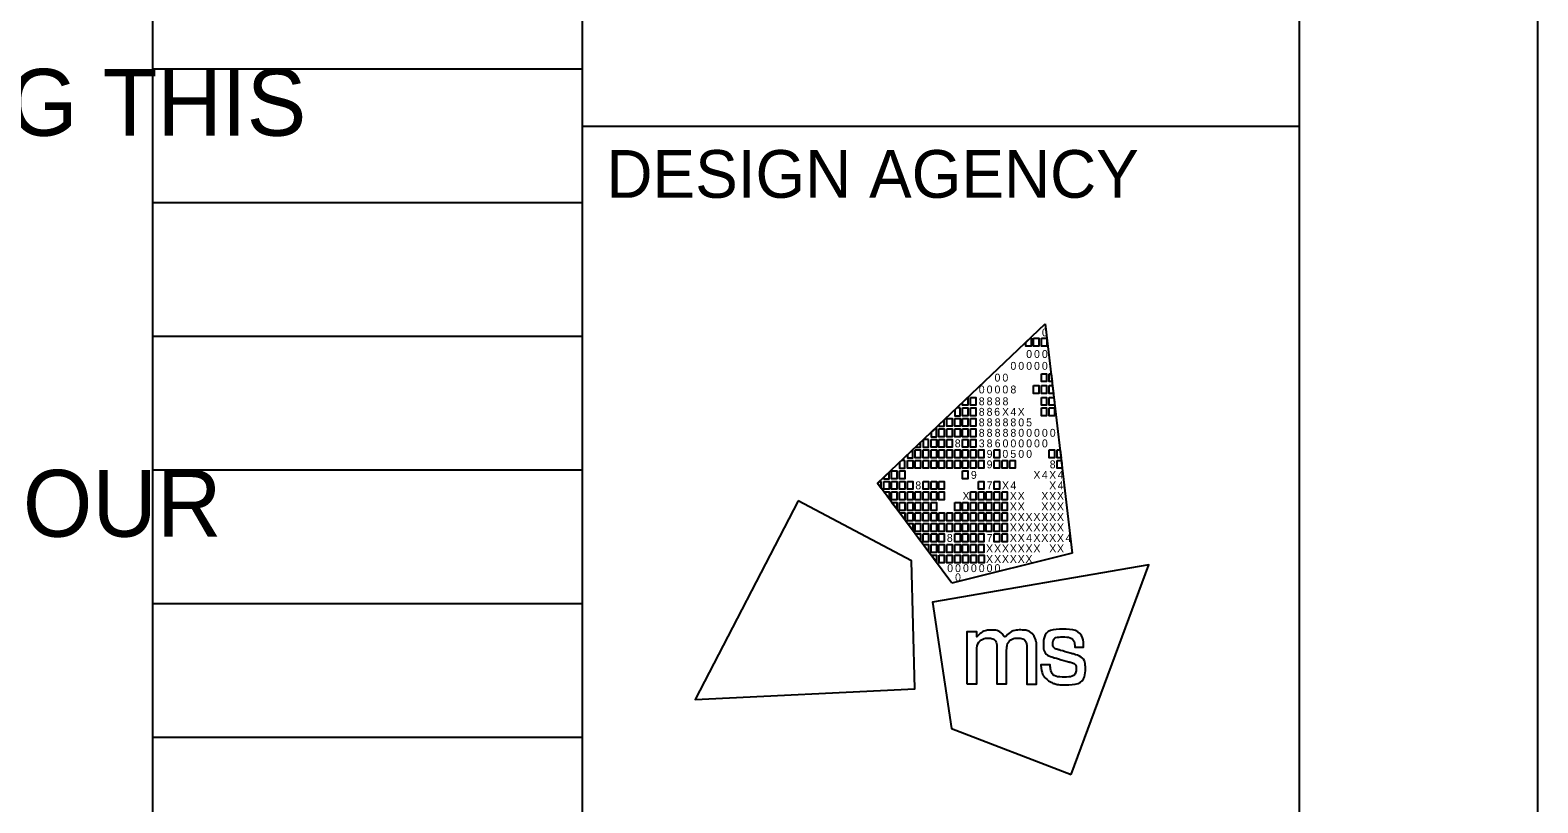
# Model space of a CAD drawing. Extents: x 0 to 34, y -9.1 to 22.
# Drawn here: x 30.843 to 34, y 3.082 to 4.701 of the extents above; entities that cross this region are included whole.
import ezdxf

# ---------------------------------------------------------------- set-up
doc = ezdxf.new("R2010")
doc.units = 0
for name, color, linetype in [('SH_Border', 7, 'Continuous'), ('SH_Cut_Line', 7, 'Continuous'), ('SH_Data', 7, 'Continuous'), ('SH_Text', 7, 'Continuous')]:
    doc.layers.add(name, color=color, linetype=linetype)

msp = doc.modelspace()

# ---------------------------------------------------------------- linework, layer by layer
at = {"layer": 'SH_Border'}
for p, q in [((32, 0.5), (32, 21.5)), ((32, 4.5), (33.5, 4.5)), ((32.6175, 3.7519), (32.9688, 4.0861)), ((32.9688, 4.0861), (32.9688, 4.0861)), ((32.9688, 4.0861), (33.0253, 3.6052)), ((32.773, 3.543), (32.6175, 3.7519)), ((33.0253, 3.6052), (32.773, 3.543))]:
    msp.add_line(p, q, dxfattribs=at)
for points in [[(1.5, 21.5), (33.5, 21.5), (33.5, 0.5), (1.5, 0.5)], [(32.9279, 4.0472), (32.9369, 4.0558), (32.9389, 4.0558), (32.9389, 4.0393), (32.9279, 4.0393)], [(32.9444, 4.0558), (32.9554, 4.0558), (32.9554, 4.0393), (32.9444, 4.0393)], [(32.9609, 4.0558), (32.9719, 4.0558), (32.9719, 4.0393), (32.9609, 4.0393)], [(32.9606, 3.9815), (32.9716, 3.9815), (32.9716, 3.965), (32.9606, 3.965)], [(32.9771, 3.9815), (32.9811, 3.9815), (32.983, 3.965), (32.9771, 3.965)], [(32.9441, 3.9567), (32.9551, 3.9567), (32.9551, 3.9402), (32.9441, 3.9402)], [(32.9606, 3.9567), (32.9716, 3.9567), (32.9716, 3.9402), (32.9606, 3.9402)], [(32.9771, 3.9567), (32.984, 3.9567), (32.9859, 3.9402), (32.9771, 3.9402)], [(32.7953, 3.9211), (32.8064, 3.9316), (32.8064, 3.9154), (32.7953, 3.9154)], [(32.8123, 3.9319), (32.8233, 3.9319), (32.8233, 3.9154), (32.8123, 3.9154)], [(32.9606, 3.9319), (32.9716, 3.9319), (32.9716, 3.9154), (32.9606, 3.9154)], [(32.9771, 3.9319), (32.9869, 3.9319), (32.9881, 3.9218), (32.9881, 3.9154), (32.9771, 3.9154)], [(32.7627, 3.8879), (32.7737, 3.8879), (32.7737, 3.8714), (32.7627, 3.8714)], [(32.7793, 3.8879), (32.7903, 3.8879), (32.7903, 3.8714), (32.7793, 3.8714)], [(32.7958, 3.9099), (32.8068, 3.9099), (32.8068, 3.8934), (32.7958, 3.8934)], [(32.7958, 3.8879), (32.8068, 3.8879), (32.8068, 3.8714), (32.7958, 3.8714)], [(32.8123, 3.9099), (32.8233, 3.9099), (32.8233, 3.8934), (32.8123, 3.8934)], [(32.8123, 3.8879), (32.8233, 3.8879), (32.8233, 3.8714), (32.8123, 3.8714)], [(32.9606, 3.9099), (32.9716, 3.9099), (32.9716, 3.8934), (32.9606, 3.8934)], [(32.9771, 3.9099), (32.9881, 3.9099), (32.9881, 3.8934), (32.9771, 3.8934)], [(32.7462, 3.8659), (32.7572, 3.8659), (32.7572, 3.8494), (32.7462, 3.8494)], [(32.7627, 3.8659), (32.7737, 3.8659), (32.7737, 3.8494), (32.7627, 3.8494)], [(32.7793, 3.8659), (32.7903, 3.8659), (32.7903, 3.8494), (32.7793, 3.8494)], [(32.7958, 3.8659), (32.8068, 3.8659), (32.8068, 3.8494), (32.7958, 3.8494)], [(32.8123, 3.8659), (32.8233, 3.8659), (32.8233, 3.8494), (32.8123, 3.8494)], [(32.6967, 3.8218), (32.7077, 3.8218), (32.7077, 3.8053), (32.6967, 3.8053)], [(32.7132, 3.8218), (32.7242, 3.8218), (32.7242, 3.8053), (32.7132, 3.8053)], [(32.7297, 3.8439), (32.7407, 3.8439), (32.7407, 3.8273), (32.7297, 3.8273)], [(32.7297, 3.8218), (32.7407, 3.8218), (32.7407, 3.8053), (32.7297, 3.8053)], [(32.7462, 3.8439), (32.7572, 3.8439), (32.7572, 3.8273), (32.7462, 3.8273)], [(32.7462, 3.8218), (32.7572, 3.8218), (32.7572, 3.8053), (32.7462, 3.8053)], [(32.7627, 3.8439), (32.7737, 3.8439), (32.7737, 3.8273), (32.7627, 3.8273)], [(32.7627, 3.8218), (32.7737, 3.8218), (32.7737, 3.8053), (32.7627, 3.8053)], [(32.7793, 3.8218), (32.7903, 3.8218), (32.7903, 3.8053), (32.7793, 3.8053)], [(32.7958, 3.8439), (32.8068, 3.8439), (32.8068, 3.8273), (32.7958, 3.8273)], [(32.7958, 3.8218), (32.8068, 3.8218), (32.8068, 3.8053), (32.7958, 3.8053)], [(32.8123, 3.8439), (32.8233, 3.8439), (32.8233, 3.8273), (32.8123, 3.8273)], [(32.8123, 3.8218), (32.8233, 3.8218), (32.8233, 3.8053), (32.8123, 3.8053)], [(32.8288, 3.8218), (32.8398, 3.8218), (32.8398, 3.8053), (32.8288, 3.8053)], [(32.8618, 3.8218), (32.8728, 3.8218), (32.8728, 3.8053), (32.8618, 3.8053)], [(32.9771, 3.8218), (32.9881, 3.8218), (32.9881, 3.8053), (32.9771, 3.8053)], [(32.9935, 3.8218), (32.9998, 3.8218), (33.0018, 3.8053), (32.9935, 3.8053)], [(32.6802, 3.7998), (32.6912, 3.7998), (32.6912, 3.7833), (32.6802, 3.7833)], [(32.6967, 3.7998), (32.7077, 3.7998), (32.7077, 3.7833), (32.6967, 3.7833)], [(32.7132, 3.7998), (32.7242, 3.7998), (32.7242, 3.7833), (32.7132, 3.7833)], [(32.7297, 3.7998), (32.7407, 3.7998), (32.7407, 3.7833), (32.7297, 3.7833)], [(32.7462, 3.7998), (32.7572, 3.7998), (32.7572, 3.7833), (32.7462, 3.7833)], [(32.7627, 3.7998), (32.7737, 3.7998), (32.7737, 3.7833), (32.7627, 3.7833)], [(32.7793, 3.7998), (32.7903, 3.7998), (32.7903, 3.7833), (32.7793, 3.7833)], [(32.7958, 3.7998), (32.8068, 3.7998), (32.8068, 3.7833), (32.7958, 3.7833)], [(32.8123, 3.7998), (32.8233, 3.7998), (32.8233, 3.7833), (32.8123, 3.7833)], [(32.8288, 3.7998), (32.8398, 3.7998), (32.8398, 3.7833), (32.8288, 3.7833)], [(32.8618, 3.7998), (32.8728, 3.7998), (32.8728, 3.7833), (32.8618, 3.7833)], [(32.8783, 3.7998), (32.8893, 3.7998), (32.8893, 3.7833), (32.8783, 3.7833)], [(32.8947, 3.7998), (32.9057, 3.7998), (32.9057, 3.7833), (32.8947, 3.7833)], [(32.9935, 3.7998), (33.0024, 3.7998), (33.0044, 3.7833), (32.9935, 3.7833)], [(32.6471, 3.7778), (32.6581, 3.7778), (32.6581, 3.7613), (32.6471, 3.7613)], [(32.6637, 3.7778), (32.6747, 3.7778), (32.6747, 3.7613), (32.6637, 3.7613)], [(32.7958, 3.7778), (32.8068, 3.7778), (32.8068, 3.7613), (32.7958, 3.7613)], [(32.6306, 3.7558), (32.6416, 3.7558), (32.6416, 3.7393), (32.6306, 3.7393)], [(32.6306, 3.7338), (32.6416, 3.7338), (32.6416, 3.72)], [(32.6471, 3.7558), (32.6581, 3.7558), (32.6581, 3.7393), (32.6471, 3.7393)], [(32.6471, 3.7338), (32.6581, 3.7338), (32.6581, 3.7173), (32.6471, 3.7173)], [(32.6637, 3.7558), (32.6747, 3.7558), (32.6747, 3.7393), (32.6637, 3.7393)], [(32.6637, 3.7338), (32.6747, 3.7338), (32.6747, 3.7173), (32.6637, 3.7173)], [(32.6802, 3.7558), (32.6912, 3.7558), (32.6912, 3.7393), (32.6802, 3.7393)], [(32.6802, 3.7338), (32.6912, 3.7338), (32.6912, 3.7173), (32.6802, 3.7173)], [(32.6967, 3.7338), (32.7077, 3.7338), (32.7077, 3.7173), (32.6967, 3.7173)], [(32.7132, 3.7558), (32.7242, 3.7558), (32.7242, 3.7393), (32.7132, 3.7393)], [(32.7132, 3.7338), (32.7242, 3.7338), (32.7242, 3.7173), (32.7132, 3.7173)], [(32.7297, 3.7558), (32.7407, 3.7558), (32.7407, 3.7393), (32.7297, 3.7393)], [(32.7297, 3.7338), (32.7407, 3.7338), (32.7407, 3.7173), (32.7297, 3.7173)], [(32.7462, 3.7558), (32.7572, 3.7558), (32.7572, 3.7393), (32.7462, 3.7393)], [(32.7462, 3.7338), (32.7572, 3.7338), (32.7572, 3.7173), (32.7462, 3.7173)], [(32.8123, 3.7338), (32.8233, 3.7338), (32.8233, 3.7173), (32.8123, 3.7173)], [(32.8288, 3.7558), (32.8398, 3.7558), (32.8398, 3.7393), (32.8288, 3.7393)], [(32.8288, 3.7338), (32.8398, 3.7338), (32.8398, 3.7173), (32.8288, 3.7173)], [(32.8453, 3.7338), (32.8563, 3.7338), (32.8563, 3.7173), (32.8453, 3.7173)], [(32.8618, 3.7558), (32.8728, 3.7558), (32.8728, 3.7393), (32.8618, 3.7393)], [(32.8618, 3.7338), (32.8728, 3.7338), (32.8728, 3.7173), (32.8618, 3.7173)], [(32.8783, 3.7338), (32.8893, 3.7338), (32.8893, 3.7173), (32.8783, 3.7173)], [(32.6471, 3.7117), (32.6581, 3.7117), (32.6581, 3.698)], [(32.6637, 3.7117), (32.6747, 3.7117), (32.6747, 3.6952), (32.6637, 3.6952)], [(32.6802, 3.7117), (32.6912, 3.7117), (32.6912, 3.6952), (32.6802, 3.6952)], [(32.6967, 3.7117), (32.7077, 3.7117), (32.7077, 3.6952), (32.6967, 3.6952)], [(32.7132, 3.7117), (32.7242, 3.7117), (32.7242, 3.6952), (32.7132, 3.6952)], [(32.7297, 3.7117), (32.7407, 3.7117), (32.7407, 3.6952), (32.7297, 3.6952)], [(32.7793, 3.7117), (32.7903, 3.7117), (32.7903, 3.6952), (32.7793, 3.6952)], [(32.7958, 3.7117), (32.8068, 3.7117), (32.8068, 3.6952), (32.7958, 3.6952)], [(32.8123, 3.7117), (32.8233, 3.7117), (32.8233, 3.6952), (32.8123, 3.6952)], [(32.8288, 3.7117), (32.8398, 3.7117), (32.8398, 3.6952), (32.8288, 3.6952)], [(32.8453, 3.7117), (32.8563, 3.7117), (32.8563, 3.6952), (32.8453, 3.6952)], [(32.8618, 3.7117), (32.8728, 3.7117), (32.8728, 3.6952), (32.8618, 3.6952)], [(32.8783, 3.7117), (32.8893, 3.7117), (32.8893, 3.6952), (32.8783, 3.6952)], [(32.6637, 3.6897), (32.6747, 3.6897), (32.6747, 3.676)], [(32.6747, 3.6897), (32.6747, 3.6897), (32.6747, 3.6897)], [(32.6802, 3.6897), (32.6912, 3.6897), (32.6912, 3.6732), (32.6802, 3.6732)], [(32.6802, 3.6677), (32.6912, 3.6677), (32.6912, 3.654)], [(32.6967, 3.6897), (32.7077, 3.6897), (32.7077, 3.6732), (32.6967, 3.6732)], [(32.6967, 3.6677), (32.7077, 3.6677), (32.7077, 3.6512), (32.6967, 3.6512)], [(32.7132, 3.6897), (32.7242, 3.6897), (32.7242, 3.6732), (32.7132, 3.6732)], [(32.7132, 3.6677), (32.7242, 3.6677), (32.7242, 3.6512), (32.7132, 3.6512)], [(32.7297, 3.6897), (32.7407, 3.6897), (32.7407, 3.6732), (32.7297, 3.6732)], [(32.7297, 3.6677), (32.7407, 3.6677), (32.7407, 3.6512), (32.7297, 3.6512)], [(32.7462, 3.6897), (32.7572, 3.6897), (32.7572, 3.6732), (32.7462, 3.6732)], [(32.7462, 3.6677), (32.7572, 3.6677), (32.7572, 3.6512), (32.7462, 3.6512)], [(32.7627, 3.6897), (32.7737, 3.6897), (32.7737, 3.6732), (32.7627, 3.6732)], [(32.7627, 3.6677), (32.7737, 3.6677), (32.7737, 3.6512), (32.7627, 3.6512)], [(32.7793, 3.6897), (32.7903, 3.6897), (32.7903, 3.6732), (32.7793, 3.6732)], [(32.7793, 3.6677), (32.7903, 3.6677), (32.7903, 3.6512), (32.7793, 3.6512)], [(32.7958, 3.6897), (32.8068, 3.6897), (32.8068, 3.6732), (32.7958, 3.6732)], [(32.7958, 3.6677), (32.8068, 3.6677), (32.8068, 3.6512), (32.7958, 3.6512)], [(32.8123, 3.6897), (32.8233, 3.6897), (32.8233, 3.6732), (32.8123, 3.6732)], [(32.8123, 3.6677), (32.8233, 3.6677), (32.8233, 3.6512), (32.8123, 3.6512)], [(32.8288, 3.6897), (32.8398, 3.6897), (32.8398, 3.6732), (32.8288, 3.6732)], [(32.8288, 3.6677), (32.8398, 3.6677), (32.8398, 3.6512), (32.8288, 3.6512)], [(32.8453, 3.6897), (32.8563, 3.6897), (32.8563, 3.6732), (32.8453, 3.6732)], [(32.8453, 3.6677), (32.8563, 3.6677), (32.8563, 3.6512), (32.8453, 3.6512)], [(32.8618, 3.6897), (32.8728, 3.6897), (32.8728, 3.6732), (32.8618, 3.6732)], [(32.8618, 3.6677), (32.8728, 3.6677), (32.8728, 3.6512), (32.8618, 3.6512)], [(32.8783, 3.6897), (32.8893, 3.6897), (32.8893, 3.6732), (32.8783, 3.6732)], [(32.8783, 3.6677), (32.8893, 3.6677), (32.8893, 3.6512), (32.8783, 3.6512)], [(32.7077, 3.6305), (32.6965, 3.6457), (32.7077, 3.6457)], [(32.7132, 3.6457), (32.7242, 3.6457), (32.7242, 3.6292), (32.7132, 3.6292)], [(32.7297, 3.6457), (32.7407, 3.6457), (32.7407, 3.6292), (32.7297, 3.6292)], [(32.7462, 3.6457), (32.7572, 3.6457), (32.7572, 3.6292), (32.7462, 3.6292)], [(32.7793, 3.6457), (32.7903, 3.6457), (32.7903, 3.6292), (32.7793, 3.6292)], [(32.7958, 3.6457), (32.8068, 3.6457), (32.8068, 3.6292), (32.7958, 3.6292)], [(32.8123, 3.6457), (32.8233, 3.6457), (32.8233, 3.6292), (32.8123, 3.6292)], [(32.8288, 3.6457), (32.8398, 3.6457), (32.8398, 3.6292), (32.8288, 3.6292)], [(32.8618, 3.6457), (32.8728, 3.6457), (32.8728, 3.6292), (32.8618, 3.6292)], [(32.8783, 3.6457), (32.8893, 3.6457), (32.8893, 3.6292), (32.8783, 3.6292)], [(32.724, 3.6082), (32.7132, 3.6237), (32.7242, 3.6237)], [(32.7297, 3.6237), (32.7407, 3.6237), (32.7407, 3.6072), (32.7297, 3.6072)], [(32.7302, 3.6017), (32.7407, 3.6017), (32.7408, 3.5875)], [(32.7462, 3.6237), (32.7572, 3.6237), (32.7572, 3.6072), (32.7462, 3.6072)], [(32.7463, 3.6017), (32.7573, 3.6017), (32.7573, 3.5852), (32.7463, 3.5852)], [(32.7627, 3.6237), (32.7737, 3.6237), (32.7737, 3.6072), (32.7627, 3.6072)], [(32.763, 3.6017), (32.774, 3.6017), (32.774, 3.5852), (32.763, 3.5852)], [(32.7793, 3.6237), (32.7903, 3.6237), (32.7903, 3.6072), (32.7793, 3.6072)], [(32.7794, 3.6017), (32.7904, 3.6017), (32.7904, 3.5852), (32.7794, 3.5852)], [(32.7958, 3.6237), (32.8068, 3.6237), (32.8068, 3.6072), (32.7958, 3.6072)], [(32.796, 3.6017), (32.807, 3.6017), (32.807, 3.5852), (32.796, 3.5852)], [(32.8123, 3.6237), (32.8233, 3.6237), (32.8233, 3.6072), (32.8123, 3.6072)], [(32.8129, 3.6017), (32.8239, 3.6017), (32.8239, 3.5851), (32.8129, 3.5851)], [(32.8288, 3.6237), (32.8398, 3.6237), (32.8398, 3.6072), (32.8288, 3.6072)], [(32.8296, 3.6017), (32.8406, 3.6017), (32.8406, 3.5851), (32.8296, 3.5851)]]:
    msp.add_lwpolyline(points, close=True, dxfattribs=at)
for points in [[(32.7572, 3.8849), (32.7462, 3.8744), (32.7462, 3.8714), (32.7572, 3.8714), (32.7572, 3.8849)], [(32.7903, 3.9099), (32.7836, 3.9099), (32.7793, 3.9058), (32.7793, 3.8934), (32.7903, 3.8934), (32.7903, 3.9099)], [(32.7407, 3.8691), (32.7297, 3.8587), (32.7297, 3.8494), (32.7407, 3.8494), (32.7407, 3.8691)], [(32.6912, 3.822), (32.6802, 3.8115), (32.6802, 3.8053), (32.6912, 3.8053), (32.6912, 3.822)], [(32.7077, 3.8377), (32.6968, 3.8273), (32.7077, 3.8273), (32.7077, 3.8377)], [(32.7242, 3.8439), (32.7141, 3.8439), (32.7132, 3.843), (32.7132, 3.8273), (32.7242, 3.8273), (32.7242, 3.8439)], [(32.6747, 3.7998), (32.6679, 3.7998), (32.6637, 3.7958), (32.6637, 3.7833), (32.6747, 3.7833), (32.6747, 3.7998)], [(32.6416, 3.7749), (32.6306, 3.7644), (32.6306, 3.7613), (32.6416, 3.7613), (32.6416, 3.7749)], [(32.6251, 3.7558), (32.6216, 3.7558), (32.6175, 3.7519), (32.6251, 3.7417), (32.6251, 3.7558)], [(32.4512, 3.7149), (32.2359, 3.2988), (32.6956, 3.3215), (32.6884, 3.5892), (32.4512, 3.7149)], [(33.0229, 3.1422), (33.1859, 3.5814), (32.7324, 3.5029), (32.7722, 3.2381), (33.0229, 3.1422)]]:
    msp.add_lwpolyline(points, dxfattribs=at)
for points in [[(32.8048, 3.3315), (32.8048, 3.3315), (32.8048, 3.4409), (32.8048, 3.4409), (32.8048, 3.4409), (32.8255, 3.4409), (32.8255, 3.4409), (32.8255, 3.4409), (32.8255, 3.4297), (32.8255, 3.4297), (32.8346, 3.4399), (32.8457, 3.4445), (32.8555, 3.4445), (32.8688, 3.4445), (32.8791, 3.4372), (32.8837, 3.4266), (32.8915, 3.4381), (32.905, 3.4446), (32.9166, 3.4446), (32.9325, 3.4446), (32.9451, 3.435), (32.9494, 3.4213), (32.9494, 3.4212), (32.9494, 3.4212), (32.9494, 3.4212), (32.9501, 3.419), (32.9506, 3.4172), (32.9506, 3.4071), (32.9506, 3.4071), (32.9506, 3.3314), (32.9506, 3.3314), (32.9506, 3.3314), (32.9303, 3.3314), (32.9303, 3.3314), (32.9303, 3.3314), (32.9303, 3.4048), (32.9303, 3.4048), (32.9303, 3.4201), (32.9219, 3.4274), (32.911, 3.4274), (32.8995, 3.4274), (32.8879, 3.4171), (32.8879, 3.4001), (32.8879, 3.4001), (32.8879, 3.3315), (32.8879, 3.3315), (32.8879, 3.3315), (32.8674, 3.3315), (32.8674, 3.3315), (32.8674, 3.3315), (32.8674, 3.4059), (32.8674, 3.4059), (32.8674, 3.4203), (32.8588, 3.4274), (32.8496, 3.4274), (32.8384, 3.4274), (32.8254, 3.417), (32.8254, 3.3962), (32.8254, 3.3962), (32.8254, 3.3315), (32.8254, 3.3315), (32.8254, 3.3315), (32.8048, 3.3315), (32.8048, 3.3315)], [(32.9595, 3.3709), (32.9595, 3.3709), (32.9595, 3.3717), (32.9595, 3.3717), (32.9595, 3.3717), (32.9603, 3.3717), (32.9603, 3.3717), (32.9603, 3.3717), (32.9783, 3.3717), (32.9783, 3.3717), (32.9783, 3.3717), (32.9789, 3.3717), (32.9789, 3.3717), (32.9789, 3.3717), (32.979, 3.371), (32.979, 3.371), (32.9803, 3.3554), (32.9887, 3.346), (33.009, 3.346), (33.0273, 3.346), (33.0333, 3.3554), (33.0333, 3.3631), (33.0333, 3.3732), (33.0256, 3.3758), (33.0175, 3.378), (33.0175, 3.378), (32.987, 3.3867), (32.987, 3.3867), (32.972, 3.3909), (32.9648, 3.4019), (32.9648, 3.4142), (32.9648, 3.4303), (32.9768, 3.4462), (33.0052, 3.4462), (33.0348, 3.4462), (33.0489, 3.4285), (33.0489, 3.4095), (33.0489, 3.4095), (33.0489, 3.4087), (33.0489, 3.4087), (33.0489, 3.4087), (33.0482, 3.4087), (33.0482, 3.4087), (33.0482, 3.4087), (33.0312, 3.4087), (33.0312, 3.4087), (33.0312, 3.4087), (33.0305, 3.4087), (33.0305, 3.4087), (33.0305, 3.4087), (33.0305, 3.4094), (33.0305, 3.4094), (33.0301, 3.4208), (33.0226, 3.43), (33.0056, 3.43), (32.9891, 3.43), (32.9843, 3.4218), (32.9843, 3.4157), (32.9843, 3.4108), (32.9869, 3.4059), (32.9959, 3.4033), (32.9959, 3.4033), (33.0255, 3.3948), (33.0255, 3.3948), (33.0462, 3.3889), (33.0527, 3.3777), (33.0527, 3.3639), (33.0527, 3.3462), (33.041, 3.3298), (33.0087, 3.3298), (32.9952, 3.3298), (32.9877, 3.3321), (32.9823, 3.3348), (32.969, 3.3414), (32.9609, 3.3536), (32.9595, 3.3709)]]:
    msp.add_open_spline(points, degree=3, dxfattribs=at)
at = {"layer": 'SH_Cut_Line'}
msp.add_lwpolyline([(0, 0), (34, 0), (34, 22), (0, 22)], close=True, dxfattribs=at)
at = {"layer": 'SH_Data'}
for p, q in [((31.1, 0.98), (31.1, 21.14)), ((32, 0.98), (32, 21.14)), ((31.1, 4.62), (32, 4.62)), ((31.1, 4.34), (32, 4.34)), ((31.1, 4.06), (32, 4.06)), ((31.1, 3.78), (32, 3.78)), ((31.1, 3.5), (32, 3.5)), ((32.75, 3.5), (32.75, 3.5)), ((31.1, 3.22), (32, 3.22))]:
    msp.add_line(p, q, dxfattribs=at)

# ---------------------------------------------------------------- texts
at = {"layer": 'SH_Border'}
for s, p in [('0', (32.9617, 4.0597)), ('0', (32.9288, 4.0145)), ('0', (32.9452, 4.0145)), ('0', (32.9617, 4.0145)), ('0', (32.8625, 3.965)), ('0', (32.879, 3.965)), ('0', (32.8958, 3.9897)), ('0', (32.9123, 3.9897)), ('0', (32.9288, 3.9897)), ('0', (32.9452, 3.9897)), ('0', (32.9617, 3.9897)), ('0', (32.8295, 3.9402)), ('0', (32.846, 3.9402)), ('0', (32.8625, 3.9402)), ('0', (32.879, 3.9402)), ('8', (32.8958, 3.9402)), ('8', (32.8295, 3.9154)), ('8', (32.846, 3.9154)), ('8', (32.8628, 3.9154)), ('8', (32.8793, 3.9154)), ('8', (32.8295, 3.8934)), ('8', (32.8295, 3.8713)), ('8', (32.846, 3.8934)), ('8', (32.846, 3.8713)), ('6', (32.8618, 3.8934)), ('8', (32.8628, 3.8713)), ('X', (32.8781, 3.8934)), ('8', (32.8794, 3.8713)), ('4', (32.8958, 3.8934)), ('8', (32.8958, 3.8713)), ('X', (32.911, 3.8934)), ('0', (32.9123, 3.8713)), ('5', (32.9287, 3.8713)), ('8', (32.8295, 3.8494)), ('8', (32.846, 3.8494)), ('8', (32.8628, 3.8494)), ('8', (32.8794, 3.8494)), ('8', (32.8958, 3.8494)), ('0', (32.9123, 3.8494)), ('0', (32.9288, 3.8494)), ('0', (32.9452, 3.8494)), ('0', (32.9617, 3.8494)), ('0', (32.9782, 3.8494)), ('8', (32.7793, 3.8273)), ('3', (32.8295, 3.8273)), ('8', (32.846, 3.8273)), ('9', (32.846, 3.8053)), ('6', (32.8629, 3.8273)), ('0', (32.879, 3.8053)), ('0', (32.8793, 3.8273)), ('5', (32.8957, 3.8053)), ('0', (32.8958, 3.8273)), ('0', (32.9123, 3.8273)), ('0', (32.9123, 3.8053)), ('0', (32.9288, 3.8273)), ('0', (32.9288, 3.8053)), ('0', (32.9452, 3.8273)), ('0', (32.9617, 3.8273)), ('9', (32.846, 3.7833)), ('8', (32.9781, 3.7833)), ('9', (32.813, 3.7613)), ('X', (32.9439, 3.7613)), ('4', (32.9617, 3.7613)), ('X', (32.9769, 3.7613)), ('4', (32.9946, 3.7613)), ('8', (32.6967, 3.7393)), ('X', (32.7955, 3.7173)), ('7', (32.846, 3.7393)), ('X', (32.8781, 3.7393)), ('X', (32.8945, 3.7173)), ('4', (32.8958, 3.7393)), ('X', (32.911, 3.7173)), ('X', (32.9604, 3.7173)), ('X', (32.9769, 3.7393)), ('X', (32.9769, 3.7173)), ('X', (32.9933, 3.7173)), ('4', (32.9946, 3.7393)), ('X', (32.8945, 3.6952)), ('X', (32.911, 3.6952)), ('X', (32.9604, 3.6952)), ('X', (32.9769, 3.6952)), ('X', (32.9933, 3.6952)), ('X', (32.8945, 3.6732)), ('X', (32.8945, 3.6512)), ('X', (32.911, 3.6732)), ('X', (32.911, 3.6512)), ('X', (32.9274, 3.6732)), ('X', (32.9274, 3.6512)), ('X', (32.9439, 3.6732)), ('X', (32.9439, 3.6512)), ('X', (32.9604, 3.6732)), ('X', (32.9604, 3.6512)), ('X', (32.9769, 3.6732)), ('X', (32.9769, 3.6512)), ('X', (32.9933, 3.6732)), ('X', (32.9933, 3.6512)), ('8', (32.7627, 3.6292)), ('7', (32.846, 3.6292)), ('X', (32.8945, 3.6292)), ('X', (32.911, 3.6292)), ('4', (32.9288, 3.6292)), ('X', (32.9439, 3.6292)), ('X', (32.9604, 3.6292)), ('X', (32.9769, 3.6292)), ('X', (32.9933, 3.6292)), ('4', (33.0111, 3.6292)), ('X', (32.8447, 3.6072)), ('X', (32.8447, 3.5851)), ('X', (32.8616, 3.6072)), ('X', (32.8616, 3.5851)), ('X', (32.878, 3.6072)), ('X', (32.878, 3.5851)), ('X', (32.8945, 3.6072)), ('X', (32.8945, 3.5851)), ('X', (32.911, 3.6072)), ('X', (32.911, 3.5851)), ('X', (32.9274, 3.6072)), ('X', (32.9274, 3.5851)), ('X', (32.9439, 3.6072)), ('X', (32.9771, 3.6072)), ('X', (32.9933, 3.6072)), ('0', (32.7634, 3.5659)), ('0', (32.7799, 3.5659)), ('0', (32.7965, 3.5659)), ('0', (32.813, 3.5659)), ('0', (32.8295, 3.5659)), ('0', (32.846, 3.5659)), ('0', (32.8625, 3.5659)), ('0', (32.7799, 3.5467))]:
    msp.add_text(s, height=0.0165, rotation=360, dxfattribs=at).set_placement(p)
at = {"layer": 'SH_Data'}
msp.add_text('DESIGN AGENCY', height=0.1, dxfattribs=at).set_placement((32.05, 4.35))
at = {"layer": 'SH_Text'}
for s, p in [('SHALL INCLUDE THE REMOVAL OF EXISTING DETOUR SIGNS ALONG THIS ', (24.66, 4.48)), ('INCLUDED IN THE LUMP SUM CONTRACT PRICE FOR ITEM 614, DETOUR ', (24.66, 3.64))]:
    msp.add_text(s, height=0.14, dxfattribs=at).set_placement(p)

doc.saveas('drawing.dxf')
